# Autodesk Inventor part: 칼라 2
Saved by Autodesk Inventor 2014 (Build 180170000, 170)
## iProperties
Created: 2026-04
Part Number: 칼라 2
Material: 일반
Document SubType Name: Modeling
Designer: dg
Density: 1 g/cm^3
Appearance: 기본값
Author: dg
Author: jhkim
Creation Date: 2026-03-27
Sending System: Autodesk Inventor 2026
Preprocessor: ST-DEVELOPER v20.1
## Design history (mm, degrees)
node "칼라 21"
node "솔리드1"
node "기준1"
